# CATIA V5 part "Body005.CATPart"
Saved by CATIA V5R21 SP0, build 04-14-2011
Part number: Body005
Definition: design
Nomenclature: Body005
Source: Unknown
Bounding box of the stored display mesh (mm): x -0.6 to 0.6, y -0.4 to 0.4, z 0 to 1
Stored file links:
  C:\Users\beatr\OneDrive\Documents\UNB\2026_1\Pi1\Componentes eletronicos\Encoder\Body005.CATPart
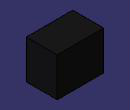
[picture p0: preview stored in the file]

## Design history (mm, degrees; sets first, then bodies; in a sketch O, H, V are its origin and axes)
Body1 "MANIFOLD_SOLID_BREP #4124" (main body)
  Solid1: solid without history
